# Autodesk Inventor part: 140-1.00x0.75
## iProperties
Created: 2009-09
Part Number: 140-1.00x0.75
Document SubType Name: Modeling
Designer: D Cole
Density: 1 g/cm^3
Translation Standard: STEP AP214IS
File Name: P:\Fastrack\52978_CRANE\Drawings\Drawings2\140-1.00x0.75.stp
Preprocessor: Autodesk Inventor 11
Postprocessor: Build: 320, Release: 2008 SP2 - Date: Mon 11/26/2007
Sent Units: MILLIMETERS
Uncertainty: 0.01
Author: D Cole
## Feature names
1. Base1
